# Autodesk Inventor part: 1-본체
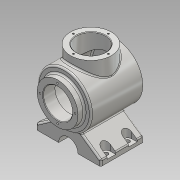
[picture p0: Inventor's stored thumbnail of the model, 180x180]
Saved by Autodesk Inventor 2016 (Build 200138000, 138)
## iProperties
Created: 2017-04
Part Number: 1-본체
Material: 알루미늄 6061
Document SubType Name: Modeling
Designer: H
Mass: 1665.04 g
Surface Area: 1068.17 cm^2
Volume: 616.68 cm^3
Density: 2.7 g/cm^3
Appearance: 알루미늄 - 평지
Author: H
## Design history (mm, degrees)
sketch "스케치1"
  geometry: L1 (-62, 0)-(-62, 38); L2 (-62, 38)-(-50, 38); L3 (-50, 38)-(-50, 50); L4 (-50, 50)-(46.336, 50); L5 (58, 0)-(-62, 0); A1 r 113 centre (-55, 0) between (58, 0) and (46.336, 50); 1 further point
  constraints: 10 end point, 3 perpendicular, 2 horizontal alignment, 2 point on circle, 1 centre point, 1 vertical
  dimensions: "d8" = 113 radius of A1; "d9" = 100 diameter of L4 L5; "d10" = 76 diameter of L2 L5; "d11" = 12 distance of L1.end L2.end; "d13" = 50 distance from line of L3 point (0, 0); "d14" = 108 distance from line of L5.start L3
revolve "회전1" sketch "스케치1" stored, may be unused: angle "d15" = 90 deg
sketch "스케치2"
  geometry: L1 (38, -62)-(-38, -62) reference; C1 r 38 at (0, 0); 1 further point
  constraints: 1 centre point, 1 coincident
  dimensions: "d16" = 76 diameter of C1
extrude "돌출1" join sketch "스케치2" distance "d17" = 65; taper "d18" = 0 deg
sketch "스케치4"
  geometry: L1 (60, -72)-(60, -82); L2 (60, -82)-(-60, -82); L3 (-60, -82)-(-60, -72); L4 (-60, -72)-(0, -29.988); L5 (0, -29.988)-(60, -72); 2 further points
  constraints: 10 end point, 2 perpendicular, 2 vertical alignment, 1 midpoint, 1 vertical
  dimensions: "d31" = 120 distance of L1.end L2.end; "d34" = 82 distance from line of L2 point (0, 0); "d35" = 55 deg angle of L3 L4; "d36" = 55 deg angle of L5 L1 (= d35); "d37" = 10 distance of L2.end L3.end
extrude "돌출2" join sketch "스케치4" distance "d38" = 42; taper "d39" = 0 deg
extrude "돌출3" join sketch "스케치4" distance "d40" = 38; taper "d41" = 0 deg
sketch "스케치3"
  geometry: L1 (-50, 50)-(46.336, 50) reference; L2 (-50, -50)-(46.336, -50) reference; L3 (-50, -50)-(-50, 50) reference; L4 (39.916, 40)-(-40, 40); L5 (-40, 40)-(-40, -40); L6 (-40, -40)-(39.916, -40); L7 (-40, 0)-(48, 0); A1 r 113 centre (-55, 0) between (46.336, -50) and (46.336, 50) reference; A2 r 103 centre (-55, 0) between (39.916, -40) and (39.916, 40); 1 further point
  constraints: 8 end point, 5 point on circle, 2 point on line, 1 centre point, 1 midpoint, 2 other
  dimensions: "d19" = 10 radial gap between concentric circles of A1 A2; "d20" = 10 distance between parallel lines of L1 L4
revolve "회전2" sketch "스케치3" stored, may be unused: angle "d21" = 90 deg
hole "구멍1" diameter "d24" = 54; stored, may be unused: countersink angle "d28" = 90 deg, drill point angle "d30" = 118 deg; dims "d22" = 10, "d23" = 10, "d25" = 6, "d26" = 4, "d27" = 2, "d29" = 8
sketch "스케치5"
  geometry: L1 (-60, -82)-(60, -82) reference; C1 r 18 at (0, -82); 2 further points
  constraints: 1 centre point, 1 coincident, 1 midpoint
  dimensions: "d42" = 18 radius of C1
extrude "돌출4" cut sketch "스케치5" stored distance "d43" = 38; taper "d44" = 0 deg
hole "구멍2" diameter "d47" = 54; stored, may be unused: countersink angle "d51" = 90 deg, drill point angle "d53" = 118 deg; dims "d45" = 10, "d46" = 10, "d48" = 6, "d49" = 4, "d50" = 2, "d52" = 8
node "작업 평면3"
sketch "스케치8"
  geometry: L1 (-50, -22)-(50, -22); L2 (50, -22)-(50, 18); L3 (50, 18)-(-50, 18); L4 (-50, 18)-(-50, -22); L5 (-18, 38)-(-60, 38) reference; L6 (-60, -42)-(-18, -42) reference; L7 (-60, 38)-(-60, -42) reference; L8 (60, 38)-(60, -42) reference; L9 (-50, 26)-(-60, 26); L10 (-50, 10)-(-60, 10); L11 (-60, 10)-(-60, 26); A1 r 8 centre (-50, 18) between (-50, 26) and (-50, 10); 1 further point
  constraints: 14 end point, 3 parallel, 3 point on line, 2 horizontal, 2 point on circle, 2 tangent, 1 centre point, 1 coincident, 1 collinear, 1 perpendicular
  dimensions: "d67" = 20 distance between parallel lines of L5 L3; "d68" = 20 distance between parallel lines of L6 L1 (= d67); "d69" = 10 distance between parallel lines of L7 L4; "d70" = 10 distance between parallel lines of L8 L2 (= d69); "d71" = 8 radius of A1
extrude "돌출6" cut sketch "스케치8" distance "d74" = 20; taper "d75" = 0 deg
hole "구멍3" diameter "d82" = 8; stored, may be unused: countersink angle "d86" = 90 deg, drill point angle "d88" = 118 deg; dims "d80" = 10, "d81" = 10, "d83" = 6, "d84" = 4, "d85" = 2, "d87" = 8
sketch "스케치10" dims "d95" = 65
  geometry: L1 (0, 0)-(0, 32.5); 1 further point
  constraints: 2 end point, 1 coincident, 1 vertical, 1 vertical alignment, 2 other
sketch "스케치11" dims "d96" = 65
  geometry: L1 (0, 0)-(0, 32.5); 1 further point
  constraints: 2 end point, 1 coincident, 1 vertical, 1 vertical alignment, 2 other
hole "구멍4" sketch "스케치11" at (0, 32.5) diameter "d97" = 3.242; stored, may be unused: countersink angle "d101" = 90 deg, drill point angle "d103" = 118 deg; dims "d98" = 8, "d99" = 4, "d100" = 2, "d102" = 10
hole "구멍5" sketch "스케치10" diameter "d104" = 3.242; stored, may be unused: countersink angle "d108" = 90 deg, drill point angle "d110" = 118 deg; dims "d105" = 8, "d106" = 4, "d107" = 2, "d109" = 10
chamfer "모따기1" distance "d117" = 1; stored, may be unused: second distance "d118" = 2, angle "d119" = 45 deg
chamfer "모따기2" distance "d120" = 1; stored, may be unused: second distance "d121" = 2, angle "d122" = 45 deg
fillet "모깎기1" dims "d128" = 3
fillet "모깎기2" dims "d129" = 3
node "작업 평면4"
sketch "스케치13"
  geometry: 2 further points
  constraints: 1 coincident, 1 other
feature "엠보싱1" sketch "스케치13" dims "d8" = 113, "d9" = 100, "d10" = 76, "d11" = 12, "d13" = 50, "d14" = 108, "d130" = 0.5, "d131" = 0
node "솔리드1"
pattern_linear "직사각형 패턴2"
mirror "대칭1"
pattern_circular "원형 패턴1" dims angle "d112" = 360 deg
pattern_circular "원형 패턴2" dims angle "d115" = 360 deg
node "투영된 루프1"
other parameters: "d66" = -76
